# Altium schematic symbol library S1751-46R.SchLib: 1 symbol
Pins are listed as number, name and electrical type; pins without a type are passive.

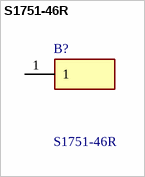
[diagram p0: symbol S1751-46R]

## S1751-46R
designator B?
Hardware: SMT Test Point 1.63x3.25mm 2mm high (T+R); Manufacturer_Name: Harwin
footprint S175146R
pins: 1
